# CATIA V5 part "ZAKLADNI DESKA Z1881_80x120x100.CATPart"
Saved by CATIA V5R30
Part number: ZAKLADNI DESKA VETSI
Bounding box of the stored display mesh (mm): x 0 to 100, y 0 to 15, z -60 to 60
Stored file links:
  C:\Users\ondra\Desktop\PŘÍLOHA P III\CATIA\ZAKLADNI DESKA Z1881_80x120x100.CATPart
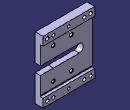
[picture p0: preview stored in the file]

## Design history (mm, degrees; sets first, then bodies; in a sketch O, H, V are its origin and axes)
Set1
  DatumSurface1 to DatumSurface58 "Z1881/80"
  Plane1: type Tangent, Support DatumSurface57, RefPoint vertex [face of DatumSurface55]
  Plane2: type Tangent, Support DatumSurface50, RefPoint vertex [face of DatumSurface57]
  Plane3: type Tangent, Support DatumSurface54, RefPoint vertex [face of DatumSurface57]
  Plane4: type Tangent, Support DatumSurface57, RefPoint vertex [face of DatumSurface57]
  Plane5: type Tangent, Support DatumSurface55, RefPoint vertex [face of DatumSurface57]
  Plane6: type Tangent, Support DatumSurface49, RefPoint vertex [face of DatumSurface57]
  Join1: Elements (DatumSurface1; DatumSurface2; DatumSurface3; DatumSurface4; DatumSurface5; DatumSurface6; DatumSurface7; DatumSurface8; DatumSurface9; DatumSurface10; DatumSurface11; DatumSurface12; DatumSurface13; DatumSurface14; DatumSurface15; DatumSurface16; DatumSurface17; DatumSurface18; DatumSurface19; DatumSurface20; DatumSurface21; DatumSurface22; DatumSurface23; DatumSurface24; DatumSurface25; DatumSurface26; DatumSurface27; DatumSurface28; DatumSurface29; DatumSurface30; DatumSurface31; DatumSurface32; DatumSurface33; DatumSurface34; DatumSurface35; DatumSurface36; DatumSurface37; DatumSurface38; DatumSurface39; DatumSurface40; DatumSurface41; DatumSurface42; DatumSurface43; DatumSurface44; DatumSurface45; DatumSurface46; DatumSurface47; DatumSurface48; DatumSurface49; DatumSurface50; DatumSurface51; DatumSurface52; DatumSurface53; DatumSurface54; DatumSurface55; DatumSurface56; DatumSurface57; DatumSurface58)
Body1 (main body)
  CloseSurface1: CloseElement Join1
  Sketch1 on zx-plane, origin (0, 0, 0), H (-1, 0, 0), V (0, 0, 1)
    reference projected line E2 (-75, 8) -> (-25, 8) from edge [face of CloseSurface1 | face of CloseSurface1]
    reference projected line E3 (-100, -60) -> (-100, 60) from edge [face of CloseSurface1 | face of CloseSurface1]
    line L1 (-75, -8) -> (-100, -8)
    line L2 (-100, -8) -> (-100, 8)
    line L3 (-100, 8) -> (-75, 8)
    line L4 (-75, 8) -> (-75, -8)
    point P8 (-100, 8)
    horizontal: L1 H, L3 H
    vertical: L2 V, L4 V
    coincidence: P8 E3, P8 E2
  Pocket1: profile Sketch1, direction (0, -1, 0), through (limit type 6)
